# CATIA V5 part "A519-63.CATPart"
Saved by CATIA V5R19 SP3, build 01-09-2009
Part number: A519-63
Bounding box of the stored display mesh (mm): x -31.477 to 31.477, y -31.453 to 31.453, z 0 to 80
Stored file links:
  C:\Users\d.catalano\Desktop\CATALOGO CAD\04 MOLLE\A519\A519-63.CATPart
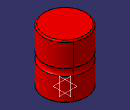
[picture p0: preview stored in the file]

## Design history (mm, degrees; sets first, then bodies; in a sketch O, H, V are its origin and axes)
Body1 "A519-63" (main body)
  Sketch1 on yz-plane, origin (0, 0, 0), H (0, 1, 0), V (0, 0, 1)
    line L1 (0, 0) -> (29.5, 0)
    line L2 (31.5, 2) -> (31.5, 34.9049)
    line L3 (29.5, 80) -> (0, 80)
    line L4 (0, 80) -> (0, 0)
    construction line L5 (-5.6038, 40) -> (28.5463, 40)
    arc A1 centre (36.3, 40) radius 7 from (31.5, 45.0951) to (31.5, 34.9049) ccw
    point P2 (36.3, 40)
    construction line L6 (29.3, 49.6338) -> (29.3, -12.4196)
    line L7 (31.5, 45.0951) -> (31.5, 78)
    arc A2 centre (29.5, 78) radius 2 from (29.5, 80) to (31.5, 78) cw
    arc A3 centre (29.5, 2) radius 2 from (29.5, 0) to (31.5, 2) ccw
    distance L4 L2 = 31.5
    distance L1 L3 = 80
    distance L5 L3 = 40
    radius A1 = 7
    distance L2 L6 = 2.2
    radius A2 = 2
    radius A3 = 2
    horizontal: L1 H, L3 H, L5 H
    vertical: L2 V, L4 V, L6 V, L7 V
    coincidence: P2 L5, L2 L7
    tangency: A1 L6, A2 L3, A2 L7, A3 L1, A3 L2
  Shaft1 "Albero": profile Sketch1, axis Sketch1.L4, angle 360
